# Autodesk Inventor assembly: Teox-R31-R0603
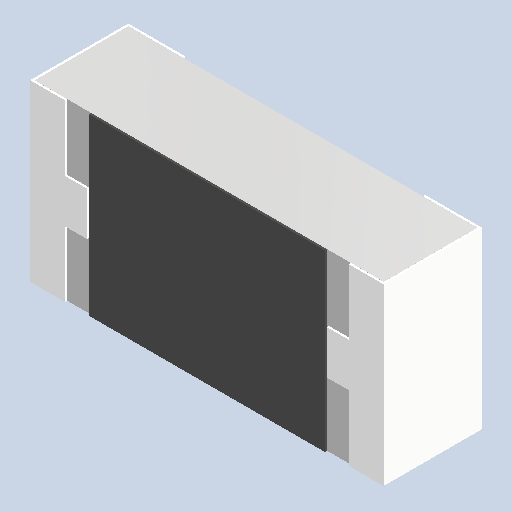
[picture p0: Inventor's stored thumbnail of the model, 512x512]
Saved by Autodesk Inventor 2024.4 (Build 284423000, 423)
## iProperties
Created: 2025-05
Part Number: Teox-R31-R0603
Document SubType Name: Assembly
Designer: AdminForWorker
Title: Teox-R31-R0603
Author: AdminForWorker
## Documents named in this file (2)
- c:\worker\convert-fusion-r02-cosv3\tmp\job-1\2\temp\files\be827049-a7f2-47ea-a815-8d9efd6bfce9\Teox-R31-R0603.iam
- c:\worker\convert-fusion-r02-cosv3\tmp\job-1\2\temp\files\be827049-a7f2-47ea-a815-8d9efd6bfce9\COMPOUND (2).ipt
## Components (1 placed, 1 different names)
1. COMPOUND (2):2
